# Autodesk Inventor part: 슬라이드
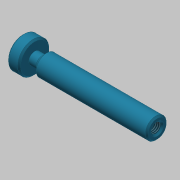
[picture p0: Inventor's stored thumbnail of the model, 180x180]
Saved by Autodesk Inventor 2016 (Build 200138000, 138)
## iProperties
Created: 2015-12
Part Number: 슬라이드
Document SubType Name: Modeling
Designer: mdu
Density: 8.08 g/cm^3
Material: 스테인리스강
Appearance: 터키옥색
Mass: 114.493 g
Surface Area: 49.8963 cm^2
Volume: 14.17 cm^3
Author: mdu
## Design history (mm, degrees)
sketch "스케치1"
  geometry: L1 (-45, 0)-(45, 0); L2 (-45, 0)-(-45, 10.5); L3 (-45, 10.5)-(-37, 10.5); L4 (-37, 10.5)-(-37, 4); L5 (-37, 4)-(-32, 4); L6 (-32, 4)-(-29, 7); L7 (-29, 7)-(45, 7); L8 (45, 7)-(45, 0); 2 further points
  constraints: 16 end point, 4 parallel, 2 perpendicular, 1 coincident, 1 horizontal, 1 midpoint
  dimensions: "d0" = 90 distance of L1.start L1.end; "d1" = 21 diameter of L3 L1; "d2" = 14 diameter of L7 L1; "d3" = 8 diameter of L5 L1; "d4" = 8 distance of L2.end L3.end; "d5" = 5 distance of L4.end L5.end; "d6" = 135 deg angle of L6 L5
revolve "회전1" sketch "스케치1" stored, may be unused: angle "d7" = 90 deg
chamfer "모따기1" distance "d8" = 1; stored, may be unused: second distance "d9" = 2, angle "d10" = 45 deg
hole "구멍1" diameter "d13" = 6.647; stored, may be unused: countersink angle "d17" = 90 deg, drill point angle "d19" = 118 deg; dims "d11" = 10, "d12" = 10, "d14" = 9, "d15" = 4, "d16" = 2, "d18" = 12
chamfer "모따기2" distance "d20" = 1; stored, may be unused: second distance "d21" = 2, angle "d22" = 45 deg
node "솔리드1"
